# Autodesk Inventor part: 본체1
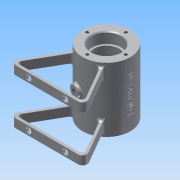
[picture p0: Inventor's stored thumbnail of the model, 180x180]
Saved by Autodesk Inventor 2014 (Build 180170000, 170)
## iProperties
Created: 2016-03
Part Number: 본체1
Material: 알루미늄 6061
Document SubType Name: Modeling
Designer: 406-16
Density: 2.71 g/cm^3
Appearance: 알루미늄 - 평지
Mass: 215.217 g
Surface Area: 337.503 cm^2
Volume: 79.416 cm^3
Author: 406-16
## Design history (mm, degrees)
sketch "스케치1"
  geometry: C1 r 26 at (0, 0); 1 further point
  constraints: 1 centre point, 1 coincident
  dimensions: "d0" = 52 diameter of C1
extrude "돌출1" new body sketch "스케치1" distance "d1" = 70; taper "d2" = 0 deg
sketch "스케치2"
  geometry: C1 r 26 at (0, 0) reference; C2 r 16 at (0, 0)
  constraints: 1 centre point, 1 coincident
  dimensions: "d3" = 32 diameter of C2
extrude "돌출2" cut sketch "스케치2" distance "d4" = 12; taper "d5" = 0 deg
sketch "스케치3"
  geometry: C1 r 16 at (0, 0) reference; C2 r 14 at (0, 0)
  constraints: 1 centre point, 1 coincident
  dimensions: "d6" = 28 diameter of C2
extrude "돌출3" cut sketch "스케치3" distance "d7" = 2; taper "d8" = 0 deg
sketch "스케치4"
  geometry: C1 r 26 at (0, 0) reference; C2 r 16 at (0, 0)
  constraints: 1 centre point, 1 coincident
  dimensions: "d9" = 32 diameter of C2
extrude "돌출4" cut sketch "스케치4" distance "d10" = 12; taper "d11" = 0 deg
sketch "스케치5"
  geometry: C1 r 16 at (0, 0) reference; C2 r 14 at (0, 0)
  constraints: 1 centre point, 1 coincident
  dimensions: "d12" = 28 diameter of C2
extrude "돌출5" cut sketch "스케치5" distance "d13" = 2; taper "d14" = 0 deg
node "작업 평면1"
sketch "스케치6"
  geometry: C1 r 21 at (0, 0); 1 further point
  constraints: 1 centre point, 1 coincident
  dimensions: "d16" = 42 diameter of C1
extrude "돌출6" cut sketch "스케치6" stored distance "d17" = 42; taper "d18" = 0 deg
node "작업 평면2"
sketch "스케치7"
  geometry: L1 (16.613, -20)-(38.264, -57.5); L2 (0, 0)-(0, -50.57); L3 (-16.613, -20)-(-38.264, -57.5); L4 (-33.934, -65)-(33.934, -65); L5 (14.015, -21.5)-(34.8, -57.5); L6 (32.202, -62)-(-32.202, -62); L7 (-34.8, -57.5)-(-14.015, -21.5); A1 r 5 centre (-33.934, -60) between (-38.264, -57.5) and (-33.934, -65); A2 r 5 centre (33.934, -60) between (33.934, -65) and (38.264, -57.5); A3 r 26 centre (0, 0) between (-16.613, -20) and (-14.183, -21.791); A4 r 26 centre (0, 0) between (14.183, -21.791) and (16.613, -20); A5 r 3 centre (-32.202, -59) between (-34.8, -57.5) and (-32.202, -62); A6 r 3 centre (32.202, -59) between (32.202, -62) and (34.8, -57.5); 3 further points
  constraints: 14 end point, 12 point on circle, 8 tangent, 6 centre point, 6 point on line, 2 symmetric about line, 1 coincident, 1 equal radius, 1 perpendicular, 1 vertical, 4 other
  dimensions: "d20" = 65 vertical distance of point (42.594, -65) point (0, 0); "d21" = 45 vertical distance of point (42.594, -65) L1.start; "d22" = 30 deg angle of L1 L2; "d23" = 3 distance between parallel lines of L7 L3; "d24" = 5 radius of A1; "d101" = 3 radius of A5; "d102" = 3 radius of A6; "d103" = 14.01517 distance from line of L5.start L2; "d104" = 29.67242 distance from line of L2.end L1; "d105" = 27.27499 distance from line of L7.end L1
extrude "돌출7" join sketch "스케치7" distance "d25" = 10; taper "d26" = 0 deg
node "작업 평면3"
sketch "스케치8"
  geometry: L1 (-26, 0)-(-26, -70) reference; L2 (-26, 0)-(26, 0) reference; C1 r 5 at (0, -35); 1 further point
  constraints: 1 centre point
  dimensions: "d28" = 10 diameter of C1; "d29" = 26 distance from line of C1.centre L1; "d30" = 35 distance from line of C1.centre L2
extrude "돌출8" join sketch "스케치8" stored distance "d31" = 3; taper "d32" = 0 deg
hole "구멍1" diameter "d35" = 5.188; stored, may be unused: countersink angle "d39" = 90 deg, drill point angle "d41" = 118 deg; dims "d33" = 10, "d34" = 10, "d36" = 20, "d37" = 4, "d38" = 2, "d40" = 25
sketch "스케치12"
  geometry: L1 (0, 21)-(0, 0); L2 (0, 0)-(21, 0); C1 r 26 at (0, 0) reference; A1 r 21 centre (0, 0) between (0, 21) and (21, 0)
  constraints: 4 end point, 2 point on circle, 1 centre point, 1 coincident, 1 perpendicular, 1 vertical
  dimensions: "d64" = 42 diameter of A1
hole "구멍3" sketch "스케치12" at (0, 21) diameter "d65" = 3.242; stored, may be unused: countersink angle "d69" = 90 deg, drill point angle "d71" = 118 deg; dims "d66" = 8, "d67" = 4, "d68" = 2, "d70" = 10
node "작업 평면5"
sketch "스케치13"
  geometry: L1 (26, 0)-(26, -70) reference; L2 (-26, 0)-(26, 0) reference; 2 further points
  constraints: 1 other
  dimensions: "d75" = 26 distance from line of point (0, -35) L1; "d76" = 35 distance from line of point (0, -35) L2
feature "엠보싱1" sketch "스케치13" dims "d77" = 0.5, "d78" = 0
sketch "스케치14"
  geometry: L1 (0, 0)-(-7.506, -28.012); L2 (0, 0)-(0, -34.845)
  constraints: 4 end point, 1 vertical
  dimensions: "d79" = 29 distance of L1.end L1.start; "d80" = 15 deg angle of L2 L1; "d81" = 9.01864 distance from line of L2.end L1
node "작업 평면6"
sketch "스케치15"
  geometry: L1 (-26, 35)-(-26, -35) reference; L2 (-26, 35)-(26, 35) reference; C1 r 6 at (0, 0); 1 further point
  constraints: 1 centre point
  dimensions: "d82" = 12 diameter of C1; "d84" = 26 distance from line of C1.centre L1; "d85" = 35 distance from line of C1.centre L2
extrude "돌출11" join sketch "스케치15" stored distance "d86" = 3; taper "d87" = 0 deg
hole "구멍4" diameter "d90" = 5.188; stored, may be unused: countersink angle "d94" = 90 deg, drill point angle "d96" = 118 deg; dims "d88" = 10, "d89" = 10, "d91" = 20, "d92" = 4, "d93" = 2, "d95" = 25
fillet "모깎기1" dims "d97" = 2
fillet "모깎기2" dims "d98" = 3
fillet "모깎기3" dims "d99" = 0.3
fillet "모깎기4" dims "d100" = 3
sketch "스케치16"
  geometry: L1 (0, 0)-(64.403, 0) reference; L2 (64.403, -10)-(0, -10) reference; C1 r 3 at (12.202, -5); C2 r 3 at (52.202, -5); 1 further point
  constraints: 2 centre point
  dimensions: "d106" = 6 diameter of C1; "d107" = 6 diameter of C2; "d108" = 20 horizontal distance of point (32.202, -15) C1.centre; "d109" = 40 distance of C2.centre C1.centre; "d110" = 5 distance from line of C1.centre L2; "d111" = 5 distance from line of L1 C2.centre
extrude "돌출12" cut sketch "스케치16" distance "d112" = 10; taper "d113" = 0 deg
fillet "모깎기5" dims "d117" = 0.5
chamfer "모따기2" distance "d118" = 1; stored, may be unused: second distance "d119" = 2, angle "d120" = 45 deg
node "솔리드1"
mirror "대칭1"
pattern_circular "원형 패턴1" dims angle "d73" = 360 deg
mirror "대칭3"
mirror "대칭4"
other parameters: "d15" = -35, "d27" = 29
